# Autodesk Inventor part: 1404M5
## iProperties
Shininess: 69.0
Length Units: 11269
Angle Units: 11279
Time Units: 11290
Mass Units: 11284
Length Display Precision: 3
Angle Display Precision: 2
Compacted: True
Company: Pneumax S.p.A.
Part Number: 1404M5
Material: Default
Description: ANELLO DOPPIO GIR. Ø4 M5
Document SubType Name: Modellazione
Catalog Web Link: www.pneumaxspa.com
Density: 1.59
Volumn: 0.8648857994912436
Area: 17.092995283760587
PropertySet Name: Model Information
Control State: 0
Master: False
Checked Out: False
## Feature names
1. Revolution6
2. Circular Pattern8
3. Circular Pattern9
4. Extrusion9
5. Extrusion10
6. Foro6 [Hole]
7. Circular Pattern10
